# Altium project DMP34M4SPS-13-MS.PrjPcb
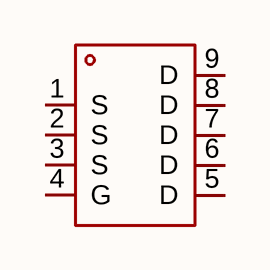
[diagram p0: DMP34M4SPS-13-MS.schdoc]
1 sheet, 1 parts. Net scope: global (net labels, ports and power ports of the same name join across sheets).

## Sheet DMP34M4SPS-13-MS.schdoc
size 127 x 101 mm

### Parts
Q?  dmp34m4sps-13-ms  [PDFN-8_L4.9-W5.8-P1.27-LS6.1-BL]  (value not drawn)

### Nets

Not connected (* = marked no-connect by the designer): Q? 1(S) 2(S) 3(S) 4(G) 5(D) 6(D) 7(D) 8(D) 9(D)

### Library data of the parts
Q? = dmp34m4sps-13-ms: 数量:1个P沟道;漏源电压(Vdss):30V;连续漏极电流(Id):100A;导通电阻(RDS(on)):3mΩ@10V;耗散功率(Pd):120W;阈值电压(Vgs(th)):1.2V;; Manufacturer: MSKSEMI(美森科); AddInBom: yes; ModelId: 178189b27e7544aca50c111426555358; ModelName: PDFN-8_L4.9-W5.8-H1.0-P1.27; ModelTransform: 200.787,240.157,0,0,0,0,-0.097,0,0; Number: 1个P沟道; Drain to Source Voltage: 30V; Current - Continuous Drain(Id): 100A; Pd - Power Dissipation: 120W; Gate Threshold Voltage (Vgs(th)): 1.2V; Gate Charge(Qg): 60nC; Input Capacitance(Ciss): 3.45nF; Reverse Transfer Capacitance (Crss@Vds): 140pF; Type: P沟道; Output Capacitance(Coss): 255pF; Vgs: ±20V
